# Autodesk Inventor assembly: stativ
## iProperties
Created: 2001-12
Part Number: stativ
Document SubType Name: Assembly
Designer: Tobben
Control State: 0
Master: False
Checked Out: False
Shininess: 64.0
Length Units: 11269
Angle Units: 11279
Time Units: 11290
Mass Units: 11283
Length Display Precision: 3
Angle Display Precision: 2
Density: 0.0
Volumn: 0.0
Area: 0.0
PropertySet Name: Model Information
Author: Tobben
